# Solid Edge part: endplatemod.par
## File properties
Author: Deepak Maini
Template: NORMENG.PAR
Last saved by: CADCIM
Revision: 2
Application: Solid Edge
Accuracy: 0.99
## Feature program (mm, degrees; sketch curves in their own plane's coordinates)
sketch for "unnamed Protrusion 1" plane through (0, 0, 0) normal (0, 0, 1) x-axis (1, 0, 0)
  line (-50.8, 46.0858) -> (-50.8, -55.5142)
  line (-50.8, -55.5142) -> (50.8, -55.5142)
  line (50.8, -55.5142) -> (50.8, 46.0858)
  line (50.8, 46.0858) -> (-50.8, 46.0858)
extrude "unnamed Protrusion 1" add finite 12.7 along +normal
sketch for "Hole_1" plane through (0, -4.7142, 12.7) normal (0, 0, 1) x-axis (1, 0, 0)
  hole centre (-38.1, -38.1) bore radius 3.175
hole "Hole_1" diameter 6.35 through
sketch for "unnamed Hole 1" plane through (0, -4.7142, 12.7) normal (0, 0, 1) x-axis (1, 0, 0)
  hole centre (38.1, -38.1) bore radius 3.175
hole "unnamed Hole 1" through
sketch for "unnamed Hole 2" plane through (0, -4.7142, 12.7) normal (0, 0, 1) x-axis (1, 0, 0)
  hole centre (38.1, 38.1) bore radius 3.175
hole "unnamed Hole 2" through
sketch for "unnamed Hole 3" plane through (0, -4.7142, 12.7) normal (0, 0, 1) x-axis (1, 0, 0)
  hole centre (-38.1, 38.1) bore radius 3.175
  dimension (linear) = 38.1
hole "unnamed Hole 3" through
pattern "unnamed Pattern 1" of "Hole_1", "unnamed Hole 1", "unnamed Hole 2", "unnamed Hole 3"
sketch for "Hole_5" plane through (0, -4.7142, 12.7) normal (0, 0, 1) x-axis (1, 0, 0)
  hole centre (0, 0) bore radius 12.7
hole "Hole_5" diameter 25.4 through
sketch for "Hole_6" plane through (0, -4.7142, 12.7) normal (0, 0, 1) x-axis (1, 0, 0)
  hole centre (-20.6375, 0) bore radius 2.3812
  dimension (linear) = 20.6375
hole "Hole_6" diameter 4.7625 through
pattern "unnamed Pattern 2" of "Hole_6"
pattern "unnamed Pattern 3"
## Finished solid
Body 1: solid body, 15 faces, 30 edges, 8 vertices.
  Faces by surface: cylinder 9, plane 6
  Edges by curve: circle 18, line 12
Bounding box of the edges (mm): 101.600 x 101.600 x 12.700, from (-50.8, -55.5142, 0) to (50.8, 46.0858, 12.7).
Cylindrical faces by radius (mm): R2.3812 x4, R3.175 x4, R12.7 x1
Planar faces by outward normal: +x 1, +y 1, +z 1, -x 1, -y 1, -z 1
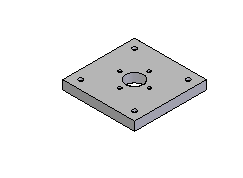
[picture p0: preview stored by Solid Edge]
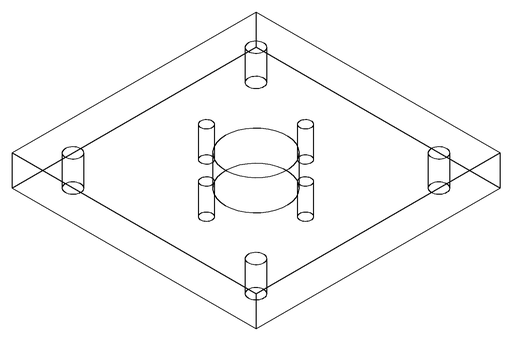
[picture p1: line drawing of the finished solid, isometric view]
